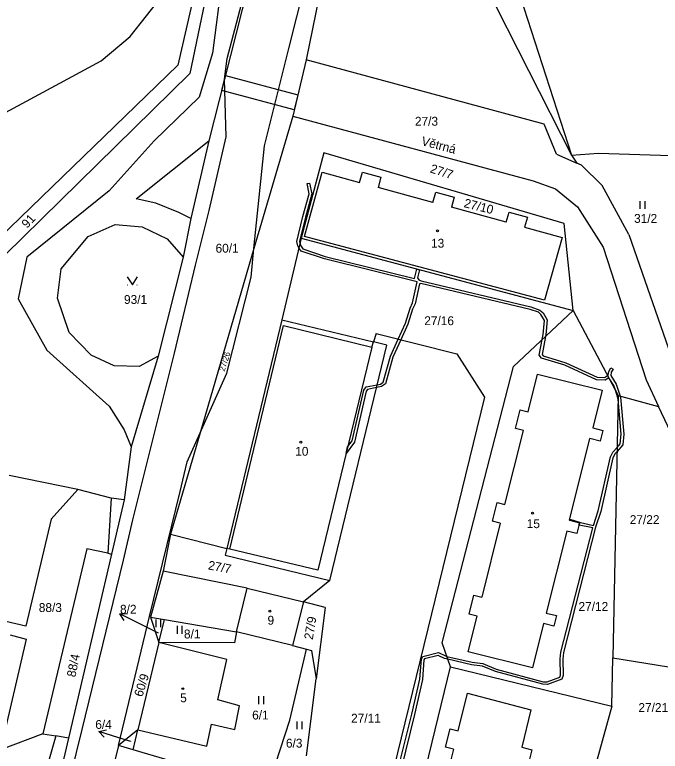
# Model space of a CAD drawing. Extents: x -670359 to -668019, y -978807 to -976674.
# Drawn here: x -670253.9 to -670130.3, y -977606.8 to -977465.8 of the extents above; entities that cross this region are included whole.
import ezdxf

# ---------------------------------------------------------------- set-up
doc = ezdxf.new("R2010")
doc.units = 0
for name, color, linetype in [('Hranice kat_území', 7, 'Continuous'), ('Hranice parcel', 7, 'Continuous'), ('Parcelní čísla', 7, 'Continuous'), ('Pop  PČ popisy', 7, 'Continuous'), ('Vnitřní kresba', 7, 'Continuous'), ('Věcná břemena k části', 7, 'Continuous'), ('Značky budov', 7, 'Continuous'), ('Značky kultur', 7, 'Continuous')]:
    doc.layers.add(name, color=color, linetype=linetype)

msp = doc.modelspace()

# ---------------------------------------------------------------- linework, layer by layer
at = {"layer": 'Hranice kat_území'}
for points in [[(-670231.74, -977469.91), (-670225.52, -977461.96)], [(-670237.29, -977474.59), (-670231.74, -977469.91)], [(-670291.52, -977503.81), (-670237.29, -977474.59)]]:
    msp.add_lwpolyline(points, dxfattribs=at)
at = {"layer": 'Hranice parcel'}
for points in [[(-670206.03, -977490.9), (-670201.37, -977472.26), (-670196.78, -977453.99), (-670188.6, -977424.41), (-670168.29, -977357.64), (-670162.97, -977342.22), (-670144.87, -977298.55), (-670137.06, -977285.54), (-670128.3, -977274.09), (-670118, -977262.95), (-670116.3, -977261.29)], [(-670213.73, -977436.69), (-670222.65, -977475.42)], [(-670212.89, -977441.17), (-670220.34, -977477.03)], [(-670193.77, -977453.38), (-670198.08, -977474.39)], [(-670213.69, -977478.11), (-670213.16, -977474.17), (-670209.3, -977459.37), (-670208.06, -977455.88)], [(-670208.06, -977455.88), (-670213.69, -977478.11)], [(-670157.8, -977460.03), (-670147.24, -977492.66)], [(-670163.73, -977460.15), (-670147.24, -977492.66)], [(-670222.65, -977475.42), (-670282.93, -977533.78)], [(-670198.08, -977474.39), (-670200.64, -977485.17)], [(-670152.47, -977486.7), (-670198.08, -977474.39)], [(-670220.34, -977477.03), (-670277.08, -977532.7)], [(-670249.31, -977636.91), (-670245.2, -977620.01), (-670240.92, -977602.66), (-670233.02, -977570.23), (-670231.23, -977562.51), (-670223.3, -977530.56), (-670219.23, -977513.75), (-670216.62, -977503.27), (-670213.37, -977489.17), (-670213.69, -977478.11)], [(-670213.69, -977478.11), (-670216.68, -977489.93)], [(-670200.64, -977485.17), (-670208.05, -977510.53)], [(-670200.64, -977485.17), (-670154.63, -977497.56)], [(-670150.12, -977492.48), (-670152.47, -977486.7)], [(-670216.68, -977489.93), (-670220.14, -977504.79)], [(-670208.05, -977510.53), (-670206.03, -977490.9)], [(-670194.67, -977492.24), (-670199.01, -977508.57)], [(-670148.67, -977505.77), (-670194.67, -977492.24)], [(-670150.12, -977492.48), (-670146.25, -977494.18)], [(-670147.24, -977492.66), (-670142.11, -977492.29)], [(-670142.11, -977492.29), (-670128.27, -977492.71)], [(-670147.24, -977492.66), (-670146.25, -977494.18)], [(-670145.33, -977494.59), (-670146.25, -977494.18)], [(-670141.36, -977498.46), (-670145.33, -977494.59)], [(-670198.4, -977508.22), (-670195.03, -977495.92)], [(-670195.03, -977495.92), (-670187.83, -977497.88)], [(-670187.83, -977497.88), (-670187.3, -977495.93)], [(-670187.3, -977495.93), (-670183.75, -977496.89)], [(-670183.75, -977496.89), (-670184.27, -977498.84)], [(-670154.63, -977497.56), (-670150.32, -977499.11)], [(-670173.78, -977501.69), (-670184.27, -977498.84)], [(-670150.32, -977499.11), (-670146.11, -977502.58)], [(-670136.3, -977507.85), (-670141.36, -977498.46)], [(-670173.78, -977501.69), (-670173.25, -977499.74)], [(-670173.25, -977499.74), (-670169.73, -977500.7)], [(-670169.73, -977500.7), (-670170.25, -977502.64)], [(-670159.74, -977505.5), (-670170.25, -977502.64)], [(-670159.74, -977505.5), (-670159.21, -977503.55)], [(-670159.21, -977503.55), (-670155.71, -977504.5)], [(-670146.11, -977502.58), (-670141.2, -977510.29)], [(-670220.14, -977504.79), (-670221.64, -977512.21)], [(-670155.71, -977504.5), (-670156.23, -977506.45)], [(-670156.23, -977506.45), (-670149.03, -977508.4)], [(-670146.94, -977522.42), (-670148.67, -977505.77)], [(-670136.3, -977507.85), (-670127.64, -977532.62)], [(-670199.01, -977508.57), (-670202.72, -977524.19)], [(-670199.01, -977508.57), (-670146.94, -977522.42)], [(-670152.4, -977520.45), (-670198.4, -977508.22)], [(-670149.03, -977508.4), (-670152.4, -977520.45)], [(-670208.05, -977510.53), (-670218.36, -977545.84)], [(-670218.36, -977545.84), (-670213.28, -977534.38), (-670208.61, -977516), (-670208.05, -977510.53)], [(-670141.2, -977510.29), (-670132.98, -977535.71)], [(-670221.64, -977512.21), (-670226.42, -977531.13)], [(-670158.38, -977533.1), (-670146.94, -977522.42)], [(-670146.94, -977522.42), (-670138.33, -977538.71)], [(-670202.72, -977524.19), (-670213.28, -977567.95)], [(-670202.72, -977524.19), (-670185.2, -977528.42)], [(-670184.69, -977526.79), (-670185.2, -977528.42)], [(-670184.69, -977526.79), (-670169.2, -977530.73)], [(-670193.51, -977574.09), (-670182.64, -977529.03)], [(-670182.64, -977529.03), (-670185.2, -977528.42)], [(-670226.42, -977531.13), (-670231.58, -977548.53)], [(-670169.2, -977530.73), (-670163.89, -977539.01)], [(-670172.02, -977586.05), (-670158.38, -977533.1)], [(-670155.57, -977541.8), (-670153.78, -977534.6)], [(-670153.78, -977534.6), (-670141.4, -977537.65)], [(-670132.98, -977535.71), (-670130.59, -977540.77)], [(-670141.4, -977537.65), (-670143.21, -977544.87)], [(-670163.89, -977539.01), (-670213.94, -977743.56)], [(-670138.33, -977538.71), (-670139.34, -977588.92)], [(-670138.33, -977538.71), (-670130.59, -977540.77)], [(-670157.98, -977545.01), (-670157.09, -977541.42)], [(-670157.09, -977541.42), (-670155.57, -977541.8)], [(-670125.26, -977552.07), (-670130.59, -977540.77)], [(-670233.99, -977605.7), (-670228.05, -977581.01), (-670222.21, -977557.07), (-670221.41, -977553.78), (-670220.82, -977551.39), (-670218.36, -977545.84)], [(-670218.36, -977545.84), (-670224.02, -977565.22)], [(-670160, -977559.54), (-670156.47, -977545.39)], [(-670156.47, -977545.39), (-670157.98, -977545.01)], [(-670143.21, -977544.87), (-670141.26, -977545.36)], [(-670141.26, -977545.36), (-670141.77, -977547.41)], [(-670147.65, -977562.58), (-670143.73, -977546.92)], [(-670141.77, -977547.41), (-670143.73, -977546.92)], [(-670231.58, -977548.53), (-670232.93, -977558.68)], [(-670241.8, -977556.7), (-670254.91, -977553.97)], [(-670241.8, -977556.7), (-670246.89, -977562.34)], [(-670235.41, -977558.34), (-670241.8, -977556.7)], [(-670232.93, -977558.68), (-670235.41, -977558.34)], [(-670232.93, -977558.68), (-670235.35, -977569.05)], [(-670162.41, -977562.76), (-670161.51, -977559.16)], [(-670161.51, -977559.16), (-670160, -977559.54)], [(-670246.89, -977562.34), (-670251.75, -977582.86)], [(-670160.9, -977563.14), (-670162.41, -977562.76)], [(-670147.65, -977562.58), (-670145.7, -977563.07)], [(-670160.9, -977563.14), (-670164.43, -977577.3)], [(-670145.7, -977563.07), (-670146.22, -977565.12)], [(-670224.02, -977565.22), (-670225.43, -977572.33)], [(-670148.17, -977564.63), (-670152.11, -977580.34)], [(-670146.22, -977565.12), (-670148.17, -977564.63)], [(-670240.04, -977568.07), (-670248.46, -977603.44)], [(-670236.05, -977568.9), (-670240.04, -977568.07)], [(-670213.28, -977567.95), (-670213.59, -977569.24)], [(-670235.35, -977569.05), (-670243.58, -977604.27)], [(-670236.05, -977568.9), (-670235.35, -977569.05)], [(-670213.59, -977569.24), (-670193.51, -977574.09)], [(-670225.43, -977572.33), (-670227.89, -977581.11)], [(-670193.51, -977574.09), (-670198.58, -977578.2)], [(-670211.43, -977583.94), (-670209.37, -977575.56)], [(-670209.37, -977575.56), (-670198.58, -977578.2)], [(-670166.85, -977580.54), (-670165.95, -977576.93)], [(-670165.95, -977576.93), (-670164.43, -977577.3)], [(-670198.58, -977578.2), (-670200.65, -977586.58)], [(-670194.43, -977579.26), (-670198.58, -977578.2)], [(-670194.43, -977579.26), (-670196.15, -977592.93)], [(-670251.75, -977582.86), (-670260.3, -977580.88)], [(-670227.89, -977581.11), (-670225.18, -977581.58)], [(-670227.89, -977581.11), (-670226.25, -977586)], [(-670167.04, -977587.77), (-670165.33, -977580.92)], [(-670165.33, -977580.92), (-670166.85, -977580.54)], [(-670152.11, -977580.34), (-670150.16, -977580.83)], [(-670150.16, -977580.83), (-670150.67, -977582.86)], [(-670226.25, -977586), (-670225.18, -977581.58)], [(-670225.18, -977581.58), (-670211.43, -977583.94)], [(-670152.62, -977582.37), (-670154.74, -977590.82)], [(-670150.67, -977582.86), (-670152.62, -977582.37)], [(-670211.43, -977583.94), (-670211.76, -977586.02)], [(-670200.65, -977586.58), (-670211.43, -977583.94)], [(-670251.69, -977585.34), (-670256.57, -977606.5)], [(-670254.73, -977584.52), (-670251.69, -977585.34)], [(-670226.25, -977586), (-670230.29, -977602.69)], [(-670211.76, -977586.02), (-670226.25, -977586)], [(-670213.23, -977589.21), (-670226.25, -977586)], [(-670200.65, -977586.58), (-670197.97, -977587.25)], [(-670170.41, -977590.62), (-670172.02, -977586.05)], [(-670203.93, -977609.27), (-670201.17, -977600.83), (-670198.43, -977589.2), (-670197.97, -977587.25)], [(-670197.97, -977587.25), (-670197.05, -977587.48)], [(-670197.05, -977587.48), (-670196.15, -977592.93)], [(-670154.74, -977590.82), (-670167.04, -977587.77)], [(-670214.96, -977596.96), (-670213.23, -977589.21)], [(-670139.52, -977598.15), (-670139.34, -977588.92)], [(-670139.34, -977588.92), (-670122.35, -977591.65)], [(-670185.19, -977651.24), (-670170.41, -977590.62)], [(-670170.41, -977590.62), (-670139.52, -977598.15)], [(-670198.01, -977607.66), (-670196.15, -977592.93)], [(-670168.97, -977602.87), (-670167.18, -977595.69)], [(-670167.18, -977595.69), (-670155.04, -977598.89)], [(-670210.81, -977598.11), (-670214.96, -977596.96)], [(-670211.72, -977602.66), (-670210.81, -977598.11)], [(-670139.52, -977598.15), (-670142.41, -977608.56)], [(-670155.04, -977598.89), (-670156.8, -977606.05)], [(-670217.11, -977605.82), (-670216.2, -977601.59)], [(-670216.2, -977601.59), (-670211.72, -977602.66)], [(-670171.36, -977606.04), (-670170.48, -977602.5)], [(-670170.48, -977602.5), (-670168.97, -977602.87)], [(-670248.46, -977603.44), (-670256.57, -977606.5)], [(-670245.98, -977603.86), (-670252.06, -977625.01)], [(-670248.46, -977603.44), (-670245.98, -977603.86)], [(-670243.58, -977604.27), (-670245.98, -977603.86)], [(-670230.29, -977602.69), (-670233.99, -977605.7)], [(-670231.18, -977606.53), (-670230.29, -977602.69)], [(-670230.29, -977602.69), (-670217.11, -977605.82)], [(-670243.58, -977604.27), (-670249.7, -977630.46)], [(-670233.99, -977605.7), (-670240.51, -977632.21)], [(-670231.18, -977606.53), (-670233.99, -977605.7)], [(-670205.49, -977614.1), (-670231.18, -977606.53)], [(-670169.86, -977606.42), (-670173.36, -977620.47)], [(-670169.86, -977606.42), (-670171.36, -977606.04)], [(-670156.8, -977606.05), (-670154.87, -977606.52)], [(-670154.87, -977606.52), (-670155.37, -977608.55)]]:
    msp.add_lwpolyline(points, dxfattribs=at)
at = {"layer": 'Parcelní čísla'}
for p, q in [((-670232.93, -977581.74), (-670233.76, -977580.49)), ((-670226.32, -977584.21), (-670230.18, -977582.28)), ((-670236.75, -977604.11), (-670237.76, -977603.01)), ((-670231.62, -977604.94), (-670233.95, -977604.21))]:
    msp.add_line(p, q, dxfattribs=at)
for points in [[(-670230.18, -977582.28), (-670233.76, -977580.49), (-670232.26, -977580.4)], [(-670233.95, -977604.21), (-670237.76, -977603.01), (-670236.3, -977602.68)]]:
    msp.add_lwpolyline(points, dxfattribs=at)
at = {"layer": 'Vnitřní kresba'}
for points in [[(-670214.13, -977458.76), (-670216, -977473.14)], [(-670216, -977473.14), (-670218.54, -977481.52)], [(-670218.54, -977481.52), (-670227.16, -977489.94)], [(-670227.16, -977489.94), (-670235.79, -977499.48)], [(-670230.6, -977501.03), (-670216.68, -977489.93)], [(-670235.79, -977499.48), (-670251.57, -977512.16)], [(-670226.85, -977501.86), (-670230.6, -977501.03)], [(-670222.46, -977503.65), (-670226.85, -977501.86)], [(-670220.14, -977504.79), (-670222.46, -977503.65)], [(-670239.77, -977508.25), (-670234.64, -977505.96)], [(-670234.64, -977505.96), (-670229.44, -977506.4)], [(-670229.44, -977506.4), (-670224.65, -977508.67)], [(-670244.94, -977514.45), (-670239.77, -977508.25)], [(-670224.65, -977508.67), (-670221.64, -977512.21)], [(-670251.57, -977512.16), (-670253.22, -977520.15)], [(-670245.7, -977520.04), (-670244.94, -977514.45)], [(-670253.22, -977520.15), (-670247.69, -977530.03)], [(-670243.43, -977526.62), (-670245.7, -977520.04)], [(-670212.68, -977568.1), (-670202.37, -977525.3)], [(-670202.37, -977525.3), (-670185.51, -977529.42)], [(-670239.22, -977530.96), (-670243.43, -977526.62)], [(-670185.51, -977529.42), (-670185.2, -977528.42)], [(-670247.69, -977530.03), (-670235.77, -977540.75)], [(-670185.51, -977529.42), (-670195.82, -977572.14)], [(-670234.83, -977532.99), (-670239.22, -977530.96)], [(-670226.42, -977531.13), (-670230.03, -977533.11)], [(-670230.03, -977533.11), (-670234.83, -977532.99)], [(-670235.77, -977540.75), (-670232.92, -977545.24)], [(-670232.92, -977545.24), (-670231.58, -977548.53)], [(-670235.41, -977558.34), (-670236.05, -977568.9)], [(-670224.02, -977565.22), (-670213.28, -977567.95)], [(-670212.68, -977568.1), (-670213.28, -977567.95)], [(-670195.82, -977572.14), (-670212.68, -977568.1)], [(-670209.37, -977575.56), (-670225.43, -977572.33)]]:
    msp.add_lwpolyline(points, dxfattribs=at)
at = {"layer": 'Věcná břemena k části'}
for p, q in [((-670197.9, -977498.11), (-670197.41, -977498)), ((-670197.5, -977500.05), (-670197.9, -977498.11)), ((-670197.41, -977498), (-670196.98, -977500.07)), ((-670198.67, -977504.38), (-670197.5, -977500.05)), ((-670196.98, -977500.07), (-670198.19, -977504.5)), ((-670199.83, -977509.22), (-670198.67, -977504.38)), ((-670198.19, -977504.5), (-670199.31, -977509.22)), ((-670199.66, -977510.04), (-670199.83, -977509.22)), ((-670199.31, -977509.22), (-670199.24, -977509.55)), ((-670199.44, -977510.38), (-670199.66, -977510.04)), ((-670199.03, -977511.01), (-670199.44, -977510.38)), ((-670199.24, -977509.55), (-670199.18, -977509.84)), ((-670199.18, -977509.84), (-670198.71, -977510.59)), ((-670198.71, -977510.59), (-670194.42, -977512.06)), ((-670194.56, -977512.54), (-670199.03, -977511.01)), ((-670194.42, -977512.06), (-670177.3, -977516.3)), ((-670176.82, -977516.93), (-670194.56, -977512.54)), ((-670177.3, -977516.3), (-670176.85, -977514.46)), ((-670176.85, -977514.46), (-670176.37, -977514.59)), ((-670176.37, -977514.59), (-670176.75, -977516.15)), ((-670176.75, -977516.15), (-670176.51, -977516.51)), ((-670176.51, -977516.51), (-670176.07, -977516.71)), ((-670177.7, -977520.95), (-670176.82, -977516.93)), ((-670176.39, -977517.31), (-670177.22, -977521.11)), ((-670176.13, -977517.21), (-670176.39, -977517.31)), ((-670155.18, -977522.21), (-670176.13, -977517.21)), ((-670176.07, -977516.71), (-670155.04, -977521.73)), ((-670179.03, -977524.81), (-670178.17, -977521.94)), ((-670177.71, -977522.12), (-670178.57, -977524.99)), ((-670178.17, -977521.94), (-670177.7, -977520.95)), ((-670177.22, -977521.11), (-670177.71, -977522.12)), ((-670155.04, -977521.73), (-670153.31, -977522.31)), ((-670153.57, -977522.75), (-670155.18, -977522.21)), ((-670153.11, -977523.18), (-670153.57, -977522.75)), ((-670153.31, -977522.31), (-670152.71, -977522.86)), ((-670152.42, -977524.32), (-670153.11, -977523.18)), ((-670152.71, -977522.86), (-670151.9, -977524.2)), ((-670180.43, -977527.87), (-670179.03, -977524.81)), ((-670152.68, -977526.97), (-670152.42, -977524.32)), ((-670151.9, -977524.2), (-670152.18, -977527.05)), ((-670178.57, -977524.99), (-670179.94, -977528)), ((-670152.24, -977527.37), (-670152.9, -977530.83)), ((-670152.87, -977527.95), (-670152.68, -977526.97)), ((-670152.18, -977527.05), (-670152.24, -977527.37)), ((-670181.93, -977531.15), (-670180.43, -977527.87)), ((-670179.94, -977528), (-670181.45, -977531.33)), ((-670153.44, -977530.95), (-670152.87, -977527.95)), ((-670183.3, -977536.13), (-670181.93, -977531.15)), ((-670181.45, -977531.33), (-670182.86, -977536.43)), ((-670153.01, -977531.52), (-670153.44, -977530.95)), ((-670148.51, -977532.87), (-670153.01, -977531.52)), ((-670152.9, -977530.83), (-670152.71, -977531.08)), ((-670152.71, -977531.08), (-670148.33, -977532.41)), ((-670142.46, -977535.65), (-670148.51, -977532.87)), ((-670148.33, -977532.41), (-670142.34, -977535.15)), ((-670140.14, -977534.07), (-670139.74, -977533.38)), ((-670139.74, -977533.38), (-670139.31, -977533.63)), ((-670140.94, -977535.25), (-670140.37, -977534.85)), ((-670140.37, -977534.85), (-670140.23, -977534.76)), ((-670140.23, -977534.76), (-670140.14, -977534.07)), ((-670139.66, -977534.23), (-670139.74, -977534.84)), ((-670139.74, -977534.84), (-670138.69, -977536.53)), ((-670139.31, -977533.63), (-670139.66, -977534.23)), ((-670183.82, -977536.51), (-670183.3, -977536.13)), ((-670140.8, -977535.77), (-670142.46, -977535.65)), ((-670142.34, -977535.15), (-670140.94, -977535.25)), ((-670140.13, -977535.3), (-670140.8, -977535.77)), ((-670139.15, -977536.75), (-670140.13, -977535.3)), ((-670189.25, -977547.39), (-670187.05, -977537.66)), ((-670187.05, -977537.66), (-670186.59, -977537.05)), ((-670186.59, -977537.05), (-670184.48, -977536.64)), ((-670186.31, -977537.51), (-670186.59, -977537.88)), ((-670184.6, -977537.17), (-670186.31, -977537.51)), ((-670183.62, -977536.97), (-670184.6, -977537.17)), ((-670184.48, -977536.64), (-670183.82, -977536.51)), ((-670182.86, -977536.43), (-670183.62, -977536.97)), ((-670138.78, -977537.86), (-670139.15, -977536.75)), ((-670138.69, -977536.53), (-670137.93, -977538.82)), ((-670186.59, -977537.88), (-670188.79, -977547.61)), ((-670138.34, -977539.38), (-670138.78, -977537.86)), ((-670137.93, -977538.82), (-670137.87, -977538.99)), ((-670137.87, -977538.99), (-670137.24, -977546.06)), ((-670137.74, -977546.06), (-670138.34, -977539.38)), ((-670137.94, -977547.93), (-670137.74, -977546.06)), ((-670137.24, -977546.06), (-670137.46, -977548.13)), ((-670190.12, -977548.54), (-670189.25, -977547.39)), ((-670188.79, -977547.61), (-670190.42, -977549.76)), ((-670190.42, -977549.76), (-670190.12, -977548.54)), ((-670139.32, -977549.52), (-670138.53, -977548.61)), ((-670137.46, -977548.13), (-670138.54, -977549.39)), ((-670138.53, -977548.61), (-670137.94, -977547.93)), ((-670139.81, -977550.45), (-670139.32, -977549.52)), ((-670138.9, -977549.8), (-670139.33, -977550.63)), ((-670138.54, -977549.39), (-670138.9, -977549.8)), ((-670142.15, -977560.75), (-670139.81, -977550.45)), ((-670139.33, -977550.63), (-670141.67, -977560.89)), ((-670143.07, -977563.56), (-670142.15, -977560.75)), ((-670141.67, -977560.89), (-670142.66, -977563.92)), ((-670147.65, -977562.58), (-670147.59, -977562.34)), ((-670145.7, -977563.07), (-670147.65, -977562.58)), ((-670147.59, -977562.34), (-670145.51, -977563.03)), ((-670145.51, -977563.03), (-670143.07, -977563.56)), ((-670149.28, -977587.8), (-670143.21, -977564.04)), ((-670142.66, -977563.92), (-670148.78, -977587.9)), ((-670145.8, -977563.48), (-670145.7, -977563.07)), ((-670143.21, -977564.04), (-670145.8, -977563.48)), ((-670175.74, -977588.67), (-670172.74, -977587.9)), ((-670172.8, -977588.44), (-670175.42, -977589.11)), ((-670171.57, -977589.04), (-670172.8, -977588.44)), ((-670172.74, -977587.9), (-670171.41, -977588.56)), ((-670149.44, -977589.13), (-670149.28, -977587.8)), ((-670148.78, -977587.9), (-670148.94, -977589.15)), ((-670176.32, -977592.97), (-670176.01, -977589.11)), ((-670176.01, -977589.11), (-670175.74, -977588.67)), ((-670175.53, -977589.27), (-670175.82, -977593.05)), ((-670175.42, -977589.11), (-670175.53, -977589.27)), ((-670170.91, -977589.19), (-670171.57, -977589.04)), ((-670171.41, -977588.56), (-670171.11, -977588.63)), ((-670171.11, -977588.63), (-670166.3, -977589.76)), ((-670166.38, -977590.26), (-670170.91, -977589.19)), ((-670166.3, -977589.76), (-670164.21, -977590.03)), ((-670149.34, -977592.22), (-670149.44, -977589.13)), ((-670148.94, -977589.15), (-670148.84, -977592.32)), ((-670164.33, -977590.51), (-670166.38, -977590.26)), ((-670161.82, -977591.54), (-670164.33, -977590.51)), ((-670164.21, -977590.03), (-670161.66, -977591.06)), ((-670161.66, -977591.06), (-670152.66, -977593.48)), ((-670152.74, -977593.98), (-670161.82, -977591.54)), ((-670151.94, -977593.51), (-670149.52, -977592.62)), ((-670149.52, -977592.62), (-670149.34, -977592.22)), ((-670148.84, -977592.32), (-670149.14, -977593.02)), ((-670177.8, -977599.67), (-670176.32, -977592.97)), ((-670175.82, -977593.05), (-670177.32, -977599.79)), ((-670151.86, -977594.01), (-670152.74, -977593.98)), ((-670152.66, -977593.48), (-670151.94, -977593.51)), ((-670149.14, -977593.02), (-670151.86, -977594.01)), ((-670182.28, -977617.59), (-670177.8, -977599.67)), ((-670177.32, -977599.79), (-670181.73, -977617.45))]:
    msp.add_line(p, q, dxfattribs=at)
msp.add_lwpolyline([(-670213.5, -977477.39), (-670199.67, -977481.08), (-670200.36, -977484), (-670214.24, -977480.3), (-670213.5, -977477.39)], dxfattribs=at)
at = {"layer": 'Značky budov'}
for centre in [(-670172.92, -977507.14), (-670199.09, -977547.62), (-670154.71, -977561.2), (-670205, -977579.97), (-670221.68, -977594.82)]:
    msp.add_circle(centre, 0.175, dxfattribs=at)
at = {"layer": 'Značky kultur'}
for p, q in [((-670134.15, -977501.45), (-670134.15, -977502.95)), ((-670133.15, -977502.95), (-670133.15, -977501.45)), ((-670232.29, -977517.47), (-670232.19, -977517.47)), ((-670230.49, -977517.47), (-670230.39, -977517.47)), ((-670226.86, -977581.55), (-670226.86, -977583.05)), ((-670225.86, -977583.05), (-670225.86, -977581.55)), ((-670222.79, -977582.79), (-670222.79, -977584.29)), ((-670221.79, -977584.29), (-670221.79, -977582.79)), ((-670207.18, -977596.27), (-670207.18, -977597.77)), ((-670206.18, -977597.77), (-670206.18, -977596.27)), ((-670199.84, -977601.08), (-670199.84, -977602.58)), ((-670198.84, -977602.58), (-670198.84, -977601.08))]:
    msp.add_line(p, q, dxfattribs=at)
msp.add_lwpolyline([(-670232.34, -977515.97), (-670231.34, -977517.47), (-670230.34, -977515.97)], dxfattribs=at)
for centre in [(-670172.92, -977507.14), (-670199.09, -977547.62), (-670154.71, -977561.2), (-670205, -977579.97), (-670221.68, -977594.82)]:
    msp.add_circle(centre, 0.175, dxfattribs=at)

# ---------------------------------------------------------------- texts
at = {"layer": 'Parcelní čísla'}
for s, height, p in [('27/3', 1.7, (-670177.24, -977487.02)), ('31/2', 1.7, (-670135.28, -977505.62)), ('13', 1.7, (-670174.15, -977510.37)), ('60/1', 1.7, (-670215.41, -977511.33)), ('93/1', 1.7, (-670232.94, -977521.14)), ('27/16', 1.7, (-670175.45, -977525.21)), ('10', 1.7, (-670200.16, -977550.22)), ('27/22', 1.7, (-670136.11, -977563.3)), ('15', 1.7, (-670155.84, -977564.07)), ('88/3', 1.7, (-670249.25, -977580.14)), ('27/12', 1.7, (-670145.92, -977579.92)), ('8/2', 1.7, (-670233.7, -977580.46)), ('9', 1.7, (-670205.46, -977582.57)), ('8/2', 0.1, (-670226.44, -977584.21)), ('8/1', 1.7, (-670221.46, -977585.2)), ('5', 1.7, (-670222.18, -977597.42)), ('27/21', 1.7, (-670134.45, -977599.28)), ('6/1', 1.7, (-670208.4, -977600.72)), ('27/11', 1.7, (-670189.46, -977601.33)), ('6/4', 1.7, (-670238.44, -977602.52)), ('6/4', 0.1, (-670231.74, -977604.94)), ('6/3', 1.7, (-670201.94, -977606.1))]:
    msp.add_text(s, height=height, dxfattribs=at).set_placement(p)
for s, height, rotation, p in [('27/7', 1.7, 342.2647, (-670174.46, -977495.93)), ('27/10', 1.7, 345.9638, (-670167.98, -977502.58)), ('91', 1.7, 46.9921, (-670251.49, -977506.77)), ('27/26', 1.14, 72.2214, (-670213.71, -977534.16)), ('27/7', 1.7, 349.4127, (-670216.93, -977571.96)), ('27/9', 1.7, 80.4338, (-670196.81, -977585.53)), ('88/4', 1.7, 78.7685, (-670242.25, -977592.71)), ('60/9', 1.7, 72.7108, (-670229.43, -977596.5))]:
    msp.add_text(s, height=height, rotation=rotation, dxfattribs=at).set_placement(p)
at = {"layer": 'Pop  PČ popisy'}
msp.add_text('Větrná', height=1.7, rotation=345.4766, dxfattribs=at).set_placement((-670176.12, -977490.72))

doc.saveas('drawing.dxf')
